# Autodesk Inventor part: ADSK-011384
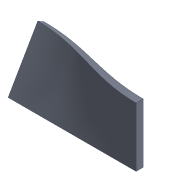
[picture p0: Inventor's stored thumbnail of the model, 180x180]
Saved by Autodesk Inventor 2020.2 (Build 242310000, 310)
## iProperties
Created: 2000-02
Part Number: ADSK-011384
Material: Pearson Stainless Steel
Document SubType Name: Modeling
Designer: gpurviance
Density: 8.03 g/cm^3
Appearance: Pearson-Stainless
Mass: 31.4779 g
Surface Area: 31.1792 cm^2
Volume: 3.92004 cm^3
Control State: 0
Checked Out: False
Master: False
Shininess: 57.0
Length Units: 11269
Angle Units: 11279
Time Units: 11290
Mass Units: 11283
Length Display Precision: 3
Angle Display Precision: 2
Compacted: True
Cutlength: * USE SCRAP FOR THIS
Material Desc: SHEET,S/S, 11 GA
Material_Number: A084638
Dimensions: 25,1x15,1x54 mm
Mass: 0,031 kg
VLT_Material: Pearson Stainless Steel
Density: 8.03
Volumn: 4.164349815588755
Area: 31.388804730404612
PropertySet Name: Model Information
Author: gpurviance
Revision Number: -
Title: ADSK-011384
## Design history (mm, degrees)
sketch "Skizze10"
  geometry: L1 (-3, 0.804)-(-3, 3.402) reference; L2 (51, 0)-(0, 0) reference; L3 (-3, 0)-(51, 0); 1 further point
  constraints: 2 collinear, 2 end point, 1 point on line
sketch "Skizze12"
  geometry: L1 (0, 23.392)-(-3, 23.392) reference; L2 (-3, 23.392)-(-3, 0) reference; L3 (0, 23.392)-(0, 0) reference; L4 (-3, 0)-(-3, -1.608); L5 (-3, -1.608)-(0, 0.124); L6 (-2.304, -1.206)-(-0.054, 0.093) reference; 2 further points
  constraints: 4 end point, 1 collinear, 1 point on line, 1 vertical
sketch "Skizze11"
  geometry: L1 (0, 0)-(3, 0) reference; L2 (0, 0)-(0, 25) reference; L3 (3, 25)-(3, 0) reference; L4 (0, 25)-(3, 25) reference; 1 further point
sketch "3D-Skizze1" dims "d25" = 10 (derived), "d26" = 10 (derived), "d27" = 10 (derived), "d28" = 10 (derived)
feature "Erhebung2" sketch "Skizze10", "Skizze12", "Skizze11", "3D-Skizze1" dims "d29" = 0, "d30" = 90 deg, "d31" = 0, "d32" = 90 deg, "d33" = 0, "d34" = 90 deg, "d35" = 0, "d36" = 90 deg, "d37" = 0, "d38" = 90 deg
node "Volumenkörper2"
feature "Fläche1"
node "Flä1"
node "Solide1"
node "Corps solides"
node "Corps surfaciques"
